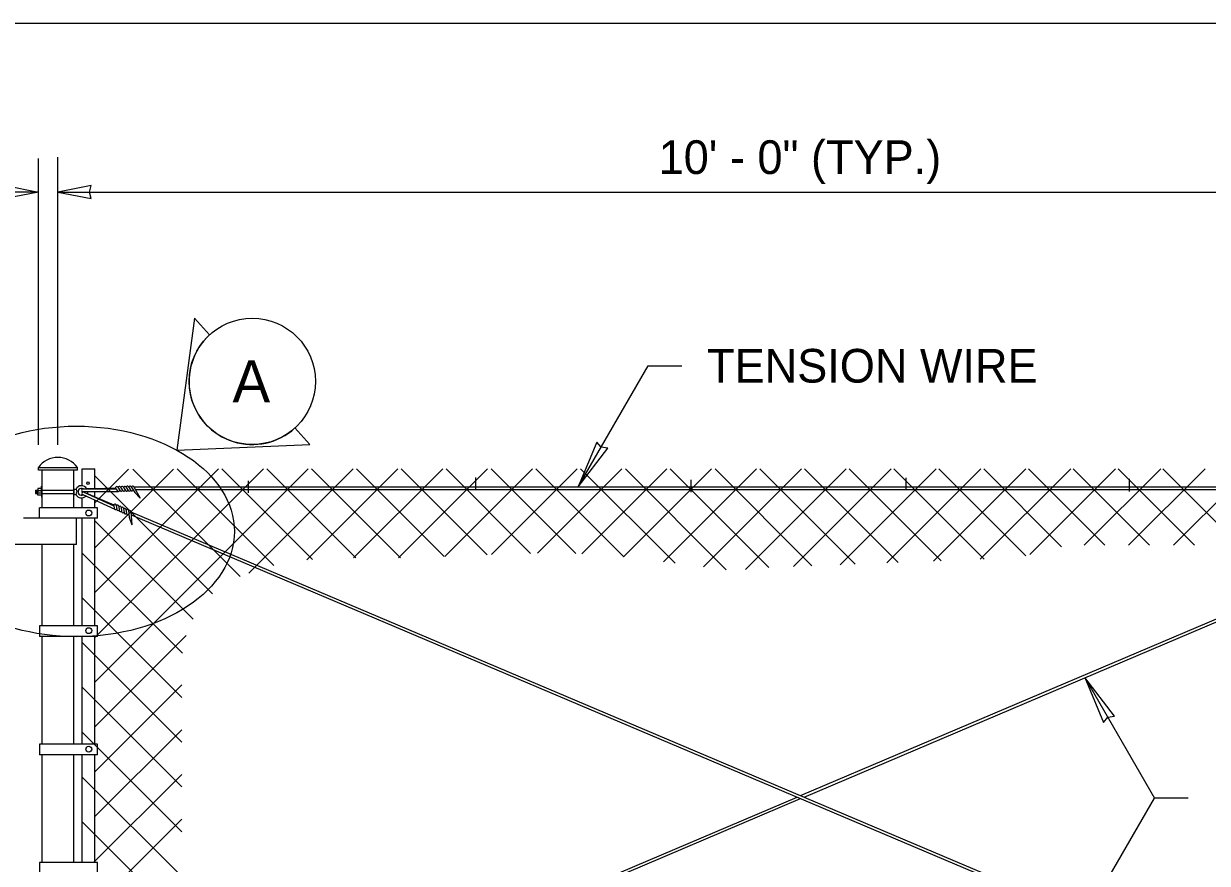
# Model space of a CAD drawing. Extents: x 99862 to 104211, y 98939 to 105076.
# Drawn here: x 102001 to 102563, y 101414 to 101813 of the extents above; entities that cross this region are included whole.
import ezdxf

# ---------------------------------------------------------------- set-up
doc = ezdxf.new("R2010")
doc.units = 0
for name, color, linetype in [('Level 11', 7, 'Continuous'), ('Level 15', 7, 'Continuous'), ('Level 2', 7, 'Continuous'), ('Level 20', 7, 'Continuous'), ('Level 4', 7, 'Continuous'), ('Level 7', 7, 'Continuous'), ('Level 9', 7, 'Continuous')]:
    doc.layers.add(name, color=color, linetype=linetype)

msp = doc.modelspace()

# ---------------------------------------------------------------- linework, layer by layer
at = {"layer": 'Level 11'}
msp.add_ellipse((102025.82, 101571.97), major_axis=(-75, 0), ratio=0.666667, dxfattribs=at)
at = {"layer": 'Level 15'}
for p, q in [((102725.47, 101813.14), (100287.45, 101813.14)), ((102017.04, 101613.16), (102017.04, 101749.74)), ((102007.82, 101613.14), (102007.82, 101749.14)), ((102007.82, 101733.14), (101005.16, 101733.14)), ((102017.04, 101733.16), (102725.47, 101733.16)), ((102264.04, 101593.18), (102297.23, 101650.66)), ((102297.23, 101650.66), (102313.23, 101650.66)), ((102504.62, 101502.55), (102537.64, 101445.35)), ((102505.14, 101389.06), (102537.64, 101445.35)), ((102553.64, 101445.35), (102537.64, 101445.35))]:
    msp.add_line(p, q, dxfattribs=at)
for points in [[(102007.82, 101733.14), (101992.09, 101730.05), (101992.82, 101733.14), (101992.09, 101736.22)], [(102017.04, 101733.16), (102032.77, 101730.08), (102032.04, 101733.16), (102032.77, 101736.24)], [(102264.04, 101593.18), (102278.04, 101611.46), (102274.92, 101612.04), (102272.87, 101614.44)], [(102504.62, 101502.55), (102513.45, 101481.29), (102515.51, 101483.7), (102518.62, 101484.27)]]:
    msp.add_lwpolyline(points, close=True, dxfattribs=at)
at = {"layer": 'Level 2'}
for p, q in [((102007.58, 101592.41), (102007.58, 101590.79)), ((102025.64, 101592.04), (102026.02, 101590.79)), ((102028.92, 101592.26), (102044.56, 101592.24)), ((102030.76, 101592.32), (102034.17, 101592.42)), ((102034.17, 101592.42), (102044.39, 101592.71)), ((102044.56, 101592.24), (102045.26, 101591.3)), ((102045.54, 101593.01), (102046.59, 101591.31)), ((102046.77, 101593.06), (102047.86, 101591.32)), ((102048.01, 101593.12), (102049.11, 101591.38)), ((102049.24, 101593.18), (102050.41, 101591.35)), ((102050.5, 101593.2), (102051.6, 101591.46)), ((102051.77, 101593.22), (102053.52, 101590.4)), ((102053.12, 101593.18), (102056.08, 101587.71)), ((102053.12, 101593.18), (102684.84, 101593.18)), ((102053.82, 101591.88), (102684.16, 101591.88)), ((102006.35, 101591.63), (102006.35, 101589.96)), ((102006.35, 101591.63), (102007.58, 101591.63)), ((102006.35, 101589.96), (102007.58, 101589.96)), ((102007, 101591.21), (102007, 101590.38)), ((102007.57, 101590.24), (102009.26, 101590.24)), ((102007.58, 101589.18), (102007.58, 101590.79)), ((102007.59, 101591.35), (102009.26, 101591.35)), ((102009.51, 101591.63), (102024.57, 101591.63)), ((102009.51, 101589.96), (102024.57, 101589.96)), ((102024.57, 101591.63), (102024.57, 101589.96)), ((102025.64, 101589.54), (102026.02, 101590.79)), ((102028.8, 101589.56), (102044.02, 101582.5)), ((102028.9, 101591.01), (102045.67, 101590.99)), ((102029.35, 101590.68), (102043.53, 101584.11)), ((102031.06, 101589.95), (102034.18, 101588.62)), ((102034.18, 101588.62), (102043.58, 101584.6)), ((102053.52, 101590.4), (102056.08, 101587.71)), ((102043.53, 101584.1), (102043.77, 101582.96)), ((102044.74, 101584.39), (102044.98, 101582.41)), ((102045.89, 101583.92), (102046.14, 101581.89)), ((102047.03, 101583.46), (102047.3, 101581.41)), ((102048.18, 101582.99), (102048.47, 101580.84)), ((102049.33, 101582.49), (102049.6, 101580.45)), ((102050.49, 101581.97), (102050.9, 101578.68)), ((102051.7, 101581.37), (102052.09, 101575.16)), ((102051.7, 101581.24), (102641.91, 101331.16)), ((102369.62, 101446.53), (102687.61, 101581.81)), ((102050.9, 101578.68), (102052.09, 101575.16)), ((102051.8, 101579.79), (102641.99, 101329.72)), ((102371.28, 101445.83), (102687.52, 101580.36)), ((102098.51, 101331.2), (102367.96, 101445.83)), ((102098.43, 101329.75), (102369.62, 101445.12))]:
    msp.add_line(p, q, dxfattribs=at)
for points in [[(102009.26, 101590.79), (102009.26, 101592.41), (102007.58, 101592.41)], [(102009.26, 101592.41), (102009.26, 101593.41), (102009.51, 101593.41)], [(102009.26, 101589.18), (102009.26, 101588.18), (102009.51, 101588.18), (102009.51, 101593.41)], [(102024.57, 101591.63), (102024.57, 101592.04), (102025.64, 101592.04)], [(102009.26, 101590.79), (102009.26, 101589.18), (102007.58, 101589.18)], [(102024.57, 101589.96), (102024.57, 101589.54), (102025.64, 101589.54)]]:
    msp.add_lwpolyline(points, dxfattribs=at)
msp.add_circle((102031.32, 101594.9), 0.625, dxfattribs=at)
for centre, radius, start, end in [((102028.27, 101590.79), 2.92, 30.2053, 154.6231), ((102028.27, 101590.79), 1.67, 58.932, 302.5071), ((102028.92, 101591.64), 0.625, 89.9247, 271.6707), ((102045.02, 101592.66), 0.625, 29.8264, 222.7101), ((102046.27, 101592.7), 0.625, 35.534, 168.7632), ((102047.52, 101592.74), 0.625, 38.2935, 168.8208), ((102048.77, 101592.77), 0.625, 40.1998, 168.9528), ((102050.01, 101592.81), 0.625, 38.9827, 169.0725), ((102051.26, 101592.85), 0.625, 36.5443, 168.9937), ((102052.57, 101592.88), 0.625, 28.4284, 175.2671), ((102028.27, 101590.79), 2.92, 205.3769, 317.1861), ((102029.08, 101590.12), 0.625, 65.1272, 246.8731), ((102028.27, 101590.79), 1.67, 347.3152, 7.0881), ((102028.27, 101590.79), 2.92, 342.0562, 4.2692), ((102045.81, 101591.6), 0.625, 208.4485, 356.3968), ((102047.12, 101591.64), 0.625, 211.6936, 348.8208), ((102048.37, 101591.68), 0.625, 209.4371, 349.894), ((102049.64, 101591.71), 0.625, 212.198, 348.993), ((102050.89, 101591.75), 0.625, 204.8409, 348.3702), ((102052.13, 101591.8), 0.625, 212.3077, 346.972), ((102044.13, 101584.3), 0.625, 5.0288, 197.9125), ((102044.4, 101583), 0.625, 183.6509, 331.5992), ((102045.28, 101583.8), 0.625, 10.7364, 143.9656), ((102045.61, 101582.48), 0.625, 186.896, 324.0232), ((102046.43, 101583.31), 0.625, 13.4959, 144.0232), ((102046.76, 101581.99), 0.625, 184.6395, 325.0964), ((102047.57, 101582.82), 0.625, 15.4022, 144.1552), ((102047.92, 101581.49), 0.625, 187.4004, 324.1954), ((102048.72, 101582.33), 0.625, 14.1852, 144.2749), ((102049.07, 101581), 0.625, 180.0433, 323.5726), ((102049.87, 101581.84), 0.625, 11.7467, 144.1961), ((102051.07, 101581.33), 0.625, 3.6308, 150.4695), ((102050.22, 101580.53), 0.625, 187.5101, 322.1744)]:
    msp.add_arc(centre, radius, start, end, dxfattribs=at)
at = {"layer": 'Level 4'}
for p, q in [((102090.41, 101542.42), (102034.51, 101598.33)), ((102034.59, 101500.41), (102135.86, 101601.68)), ((102034.59, 101542.97), (102093.31, 101601.68)), ((102034.59, 101521.68), (102114.59, 101601.68)), ((102034.59, 101564.26), (102071.89, 101601.56)), ((102034.59, 101585.54), (102050.61, 101601.56)), ((102103.56, 101550.55), (102052.56, 101601.56)), ((102119.5, 101555.83), (102073.65, 101601.68)), ((102137.92, 101558.68), (102094.92, 101601.68)), ((102107.69, 101552.23), (102157.15, 101601.68)), ((102158.48, 101559.4), (102116.2, 101601.68)), ((102135.16, 101558.42), (102178.42, 101601.68)), ((102179.74, 101559.44), (102137.5, 101601.68)), ((102157.42, 101559.4), (102199.71, 101601.68)), ((102200.36, 101560.08), (102158.76, 101601.68)), ((102178.73, 101559.43), (102220.98, 101601.68)), ((102220.79, 101560.93), (102180.04, 101601.68)), ((102200.73, 101560.1), (102242.34, 101601.68)), ((102241.45, 101561.54), (102201.31, 101601.68)), ((102215.46, 101591.77), (102215.46, 101597.53)), ((102262.95, 101561.42), (102222.73, 101601.68)), ((102222.87, 101561.01), (102263.54, 101601.68)), ((102285.72, 101559.84), (102243.88, 101601.68)), ((102244.73, 101561.59), (102284.83, 101601.68)), ((102310.01, 101556.83), (102265.16, 101601.68)), ((102265.74, 101561.32), (102306.11, 101601.68)), ((102285.56, 101559.86), (102327.38, 101601.68)), ((102334.32, 101553.79), (102286.43, 101601.68)), ((102304.51, 101557.52), (102348.68, 101601.68)), ((102354.53, 101554.87), (102307.72, 101601.68)), ((102323.45, 101555.15), (102369.99, 101601.68)), ((102375.01, 101555.66), (102328.99, 101601.68)), ((102343.53, 101553.93), (102391.3, 101601.68)), ((102395.48, 101556.45), (102350.26, 101601.68)), ((102366.29, 101555.32), (102412.65, 101601.68)), ((102415.96, 101557.24), (102371.53, 101601.68)), ((102388.43, 101556.17), (102433.93, 101601.68)), ((102436.3, 101558.02), (102392.63, 101601.68)), ((102410.58, 101557.03), (102455.24, 101601.68)), ((102456.79, 101558.81), (102413.91, 101601.68)), ((102432.71, 101557.88), (102476.51, 101601.68)), ((102476.49, 101560.38), (102435.19, 101601.68)), ((102454.88, 101558.74), (102497.84, 101601.68)), ((102493.48, 101564.69), (102456.54, 101601.68)), ((102514.06, 101565.38), (102477.76, 101601.68)), ((102478.4, 101561.01), (102519.07, 101601.68)), ((102535.33, 101565.38), (102499.03, 101601.68)), ((102504.25, 101565.38), (102540.57, 101601.68)), ((102556.61, 101565.38), (102520.31, 101601.68)), ((102525.33, 101565.38), (102561.63, 101601.68)), ((102577.89, 101565.38), (102541.59, 101601.68)), ((102546.63, 101565.38), (102582.93, 101601.68)), ((102107.53, 101590.35), (102107.53, 101596.06)), ((102317.61, 101590.66), (102317.61, 101596.48)), ((102419.76, 101591.57), (102419.76, 101597.44)), ((102525.76, 101590.97), (102525.76, 101596.91)), ((102081.21, 101530.35), (102034.59, 101576.97)), ((102076.15, 101514.12), (102028.58, 101561.7)), ((102075.82, 101493.18), (102028.58, 101540.42)), ((102075.82, 101471.9), (102028.58, 101519.15)), ((102034.59, 101479.13), (102077.96, 101522.5)), ((102075.82, 101450.64), (102028.58, 101497.94)), ((102034.59, 101457.85), (102075.82, 101499.08)), ((102075.82, 101429.33), (102028.58, 101476.58)), ((102034.74, 101436.73), (102075.82, 101477.81)), ((102075.82, 101408.06), (102028.58, 101455.3)), ((102034.31, 101415.01), (102075.82, 101456.52)), ((102034.59, 101394.05), (102075.82, 101435.25)), ((102076.95, 101385.65), (102028.58, 101434.02))]:
    msp.add_line(p, q, dxfattribs=at)
at = {"layer": 'Level 7'}
for p, q in [((102007.82, 101602.31), (102026.26, 101602.31)), ((102007.82, 101601.06), (102007.82, 101602.31)), ((102026.26, 101601.06), (102007.82, 101601.06)), ((102009.52, 101583.25), (102009.52, 101600.96)), ((102024.56, 101583.25), (102024.56, 101600.96)), ((102026.26, 101601.06), (102026.26, 101602.31)), ((102028.58, 101601.68), (102034.59, 101601.68)), ((102028.58, 101593.69), (102028.58, 101601.68)), ((102034.59, 101592.43), (102034.59, 101601.68)), ((102028.58, 101592.16), (102028.58, 101592.43)), ((102028.58, 101590.48), (102028.58, 101591.12)), ((102028.58, 101589.15), (102028.58, 101589.75)), ((102028.58, 101583.25), (102028.58, 101587.89)), ((102034.59, 101588.44), (102034.59, 101591.01)), ((102034.59, 101583.25), (102034.59, 101586.87)), ((102035.85, 101583.25), (102008.26, 101583.25)), ((102008.26, 101578.24), (102008.26, 101583.25)), ((102035.85, 101578.24), (102035.85, 101583.25)), ((102035.85, 101578.24), (102000.74, 101578.24)), ((102025.82, 101565.7), (102025.82, 101578.24)), ((102028.58, 101527.08), (102028.58, 101578.24)), ((102034.59, 101527.08), (102034.59, 101578.24)), ((102025.82, 101565.7), (101988.2, 101565.7)), ((102009.52, 101527.08), (102009.52, 101565.7)), ((102024.56, 101527.08), (102024.56, 101565.7)), ((102035.85, 101527.08), (102008.26, 101527.08)), ((102008.26, 101527.08), (102008.26, 101522.06)), ((102035.85, 101522.06), (102035.85, 101527.08)), ((102035.85, 101522.06), (102008.26, 101522.06)), ((102009.52, 101470.9), (102009.52, 101522.06)), ((102024.56, 101470.9), (102024.56, 101522.06)), ((102028.58, 101470.9), (102028.58, 101522.06)), ((102034.59, 101470.9), (102034.59, 101522.06)), ((102035.85, 101470.9), (102008.26, 101470.9)), ((102008.26, 101470.9), (102008.26, 101465.89)), ((102035.85, 101465.89), (102035.85, 101470.9)), ((102035.85, 101465.89), (102008.26, 101465.89)), ((102009.52, 101430.84), (102009.52, 101465.89)), ((102024.56, 101426.89), (102024.56, 101465.89)), ((102028.58, 101414.73), (102028.58, 101465.89)), ((102034.59, 101414.73), (102034.59, 101465.89)), ((102009.52, 101414.73), (102009.52, 101431.53)), ((102024.56, 101414.73), (102024.56, 101431.53)), ((102035.85, 101414.73), (102008.26, 101414.73)), ((102008.26, 101414.73), (102008.26, 101409.71)), ((102035.85, 101409.71), (102035.85, 101414.73))]:
    msp.add_line(p, q, dxfattribs=at)
for centre in [(102031.71, 101580.74), (102031.71, 101524.85), (102031.71, 101468.57)]:
    msp.add_circle(centre, 1.41, dxfattribs=at)
msp.add_arc((102017.04, 101595.96), 11.2, 34.5285, 145.4715, dxfattribs=at)
at = {"layer": 'Level 9'}
for p, q in [((102081.9, 101673.2), (102073.54, 101610.54)), ((102089.06, 101665.38), (102081.9, 101673.2)), ((102136.7, 101613.28), (102129.55, 101621.11)), ((102073.54, 101610.54), (102136.7, 101613.28))]:
    msp.add_line(p, q, dxfattribs=at)
msp.add_circle((102109.3, 101643.24), 30, dxfattribs=at)
msp.add_arc((102109.3, 101643.24), 30, 132.4424, 312.4468, dxfattribs=at)

# ---------------------------------------------------------------- texts
at = {"layer": 'Level 20'}
for s, height, p in [('10\' - 0" (TYP.)', 16, (102302.23, 101741.74)), ('TENSION WIRE', 16, (102325.23, 101642.66)), ('A', 20, (102099.94, 101633.31))]:
    msp.add_text(s, height=height, dxfattribs=at).set_placement(p)

doc.saveas('drawing.dxf')
